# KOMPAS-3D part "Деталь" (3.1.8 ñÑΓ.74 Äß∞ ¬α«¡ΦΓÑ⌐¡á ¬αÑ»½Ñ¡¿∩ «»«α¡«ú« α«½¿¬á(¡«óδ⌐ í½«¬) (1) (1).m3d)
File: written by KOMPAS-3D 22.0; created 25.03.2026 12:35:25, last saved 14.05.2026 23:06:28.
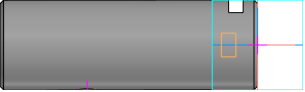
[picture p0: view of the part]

Document properties: Автор: TMK; Полное имя файла: E:\test_kompas\all_v20\3.1.8 дет.74 Ось кронштейна крепления опорного ролика(новый блок) (1) (1).m3d; Организация: TMK

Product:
- Part/product: Деталь
    Масса: 2.046242

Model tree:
1. Эскиз:1
2. Элемент выдавливания:1
     Расстояние 2 = 142
3. Фаска:1
     Угол = 45; Длина 1 = 2; Длина 2 = 2
4. Эскиз:2
5. Отверстие:2  (with: Элемент выдавливания:1)
     Глубина выреза = 99.5; Диаметр отверстия = 11.4448; Угол конуса дна = 118; Диаметр цековки = 23; Глубина цековки = 12
6. G 1/4  (with: Отверстие:2)
     Длина резьбы = 20; Шаг резьбы = 1.337; Номинальный диаметр резьбы = 13.157
7. Фаска:2
     Угол = 45; Длина 1 = 1.6; Длина 2 = 1.6
8. Смещенная плоскость:2
     Расстояние = 25
9. Эскиз:4
10. Отверстие:3
     Глубина выреза = 30.5; Диаметр отверстия = 11.5; Угол конуса дна = 118; Расстояние 2 = -94
11. Смещенная плоскость:3
     Расстояние = 25
12. Эскиз:5
13. Элемент выдавливания:3
     Расстояние 2 = 50

Expressions: cil2_6357-81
